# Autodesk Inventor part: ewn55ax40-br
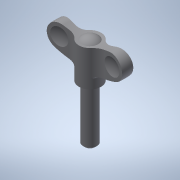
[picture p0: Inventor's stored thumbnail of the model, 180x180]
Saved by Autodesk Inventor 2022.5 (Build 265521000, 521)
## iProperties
Created: 2016-12
Part Number: ewn55ax40-br
Material: 一般
Document SubType Name: Modeling
Designer: imaocorp
Density: 1 g/cm^3
Appearance: 既定
Author: imaocorp
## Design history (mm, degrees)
node "ewn55ax40-br.x_t1"
node "ewn55ax40-br"
node "Base1"
